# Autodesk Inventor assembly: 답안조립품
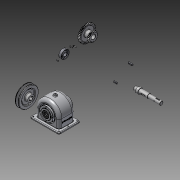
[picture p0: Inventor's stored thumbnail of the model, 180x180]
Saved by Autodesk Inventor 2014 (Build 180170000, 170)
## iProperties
Created: 2015-09
Part Number: 답안조립품
Document SubType Name: Assembly
Designer: Administrator
Author: Administrator
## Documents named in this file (14)
- C:\Users\Administrator\Desktop\450907V1048\답안조립품.iam
- C:\Users\Administrator\Desktop\450907V1048\1-본체.ipt
- C:\Users\Administrator\Desktop\450907V1048\V-벨트풀리.ipt
- C:\Users\Administrator\Desktop\450907V1048\뒤커버.ipt
- C:\Users\Administrator\Desktop\450907V1048\멈춤나사 - M4x10.ipt
- C:\Users\Administrator\Desktop\450907V1048\베어링 6203.ipt
- C:\Users\Administrator\Desktop\450907V1048\볼트 M3 x 8.ipt
- C:\Users\Administrator\Desktop\450907V1048\볼트 M3 x 10.ipt
- C:\Users\Administrator\Desktop\450907V1048\스퍼기어.ipt
- C:\Users\Administrator\Desktop\450907V1048\앞커버.ipt
- C:\Users\Administrator\Desktop\450907V1048\오일 실 17 32 8.ipt
- C:\Users\Administrator\Desktop\450907V1048\축.ipt
- C:\Users\Administrator\Desktop\450907V1048\키 - 5 x 5 x 18.ipt
- C:\Users\Administrator\Desktop\450907V1048\키 - 6 x 6 x 22.ipt
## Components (4 placed, 4 different names)
1. 1-본체:1
2. V-벨트풀리:1
3. ISO 4762 M3 x 8:1
4. ISO 4762 M3 x 10:1
